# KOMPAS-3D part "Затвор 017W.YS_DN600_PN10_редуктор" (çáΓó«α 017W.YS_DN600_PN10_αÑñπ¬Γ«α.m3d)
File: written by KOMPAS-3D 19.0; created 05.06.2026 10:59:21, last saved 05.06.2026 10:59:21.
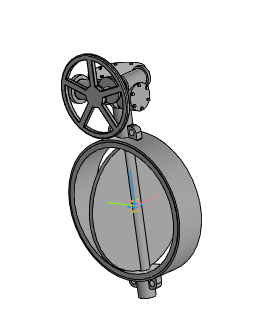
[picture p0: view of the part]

Document properties: Автор: Энергия; Полное имя файла: ..\..\..\3d для проектировщиков\x.x Тип 017W.Y(S) Затвор дисковый поворотный межфланцевый\Затвор 017W.Y(S)_DN50-DN1200_редуктор\Затвор 017W.YS_DN600_PN10_редуктор.a3d

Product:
- Part/product: Затвор 017W.YS_DN600_PN10_редуктор
    Масса: 241.864

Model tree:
1. Операция без истории:1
